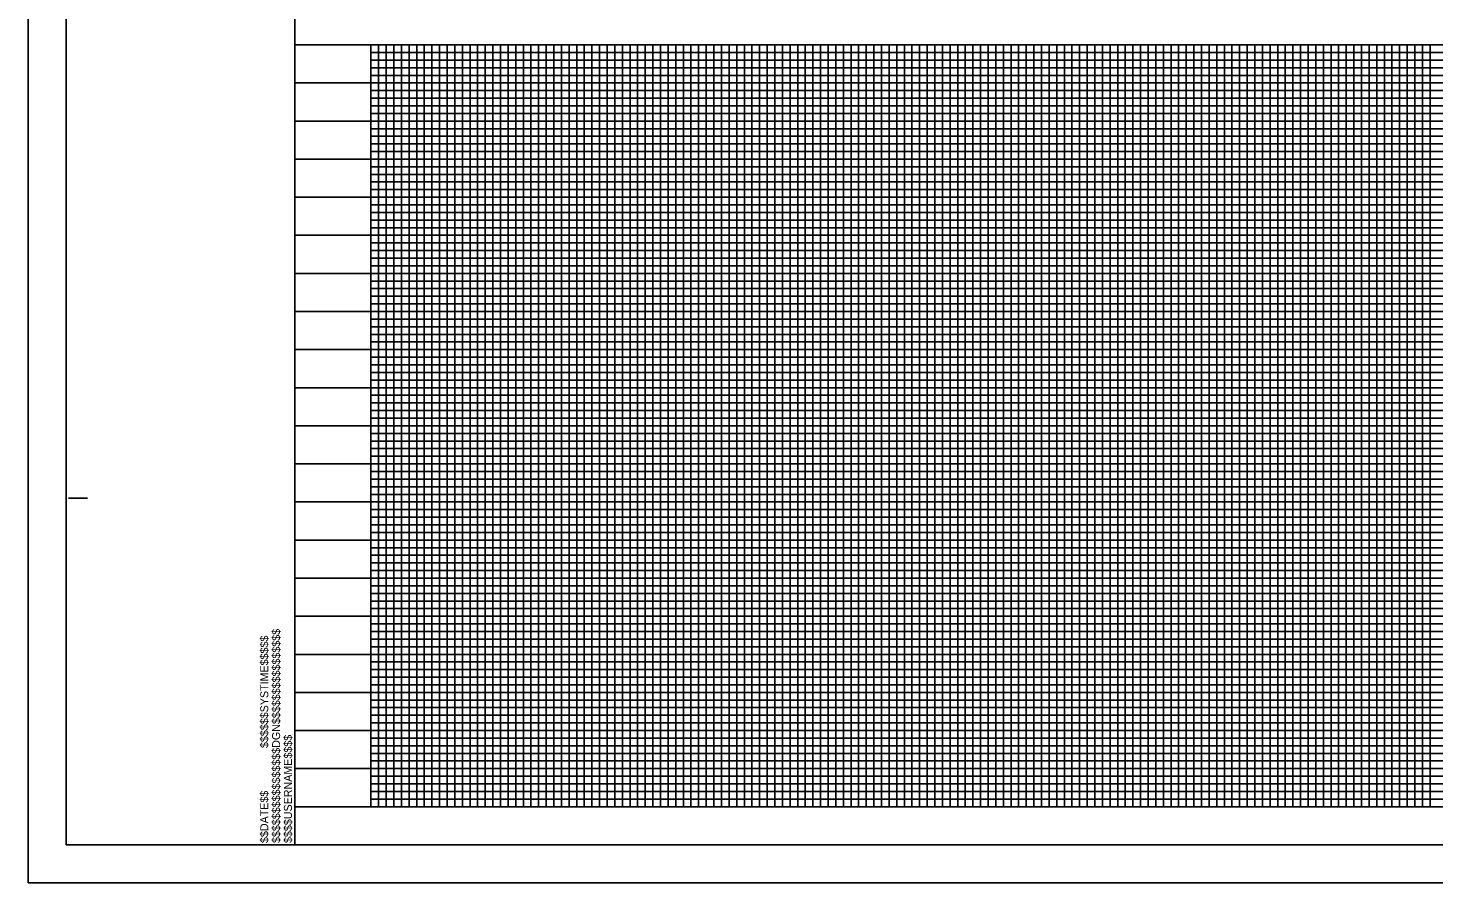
# Model space of a CAD drawing. Extents: x 2474053 to 2475957, y 620456 to 621556.
# Drawn here: x 2474053 to 2474975, y 620456 to 621017 of the extents above; entities that cross this region are included whole.
import ezdxf

# ---------------------------------------------------------------- set-up
doc = ezdxf.new("R2010")
doc.units = 0
for name, color, linetype in [('Old_Level_18', 7, 'Continuous'), ('Old_Level_40', 7, 'Continuous'), ('Old_Level_41', 7, 'Continuous'), ('Old_Level_62', 7, 'Continuous'), ('Old_Level_63', 7, 'Continuous'), ('Scratch_Level_3', 7, 'Continuous'), ('Sheet Layout Profile Border Port 2', 7, 'Continuous'), ('Sheet Profile CELL', 7, 'Continuous'), ('Sheet Profile Grid Major CELL', 7, 'Continuous'), ('Sheet Profile Grid Middle CELL', 7, 'Continuous'), ('Sheet Profile Grid Minor CELL', 7, 'Continuous')]:
    doc.layers.add(name, color=color, linetype=linetype)

msp = doc.modelspace()

# ---------------------------------------------------------------- linework, layer by layer
at = {"layer": 'Old_Level_18'}
msp.add_line((2474227.88, 620481.13), (2474227.88, 620481.13), dxfattribs=at)
msp.add_line((2474227.88, 620481.13), (2474227.88, 620481.13), dxfattribs=at)
msp.add_line((2474227.88, 620481.13), (2474227.88, 620481.13), dxfattribs=at)
msp.add_lwpolyline([(2475727.88, 621531.13), (2474227.88, 621531.13), (2474227.88, 620481.13), (2475727.88, 620481.13)], close=True, dxfattribs=at)
at = {"layer": 'Old_Level_40'}
msp.add_line((2474227.88, 620481.13), (2474227.88, 620481.13), dxfattribs=at)
msp.add_line((2474227.88, 620481.13), (2474227.88, 620481.13), dxfattribs=at)
msp.add_line((2474227.88, 620481.13), (2474227.88, 620481.13), dxfattribs=at)
msp.add_line((2474227.88, 620481.13), (2474227.88, 620481.13), dxfattribs=at)
msp.add_line((2474227.88, 620481.13), (2474227.88, 620481.13), dxfattribs=at)
at = {"layer": 'Old_Level_41'}
msp.add_line((2474079.38, 620708.63), (2474091.88, 620708.63), dxfattribs=at)
at = {"layer": 'Old_Level_62'}
msp.add_lwpolyline([(2474077.88, 620481.13), (2475727.88, 620481.13), (2475727.88, 621531.13), (2474077.88, 621531.13)], close=True, dxfattribs=at)
at = {"layer": 'Old_Level_63'}
msp.add_lwpolyline([(2474052.88, 620456.13), (2475752.88, 620456.13), (2475752.88, 621556.13), (2474052.88, 621556.13)], close=True, dxfattribs=at)
at = {"layer": 'Scratch_Level_3'}
msp.add_lwpolyline([(2474227.88, 621531.13), (2474227.88, 620481.13), (2475727.88, 620481.13), (2475727.88, 621274.49), (2475527.83, 621274.49), (2475527.83, 621531.13)], close=True, dxfattribs=at)
at = {"layer": 'Sheet Layout Profile Border Port 2'}
msp.add_lwpolyline([(2474277.88, 621006.13), (2475677.88, 621006.13), (2475677.88, 620506.13), (2474277.88, 620506.13)], close=True, dxfattribs=at)
at = {"layer": 'Sheet Profile CELL'}
for p, q in [((2474227.88, 621006.13), (2475727.88, 621006.13)), ((2475727.88, 620506.13), (2474227.88, 620506.13))]:
    msp.add_line(p, q, dxfattribs=at)
at = {"layer": 'Sheet Profile Grid Major CELL'}
for p, q in [((2474277.88, 621006.13), (2474277.88, 620506.13)), ((2474327.88, 620506.13), (2474327.88, 621006.13)), ((2474377.88, 621006.13), (2474377.88, 620506.13)), ((2474427.88, 620506.13), (2474427.88, 621006.13)), ((2474477.88, 621006.13), (2474477.88, 620506.13)), ((2474527.88, 620506.13), (2474527.88, 621006.13)), ((2474577.88, 621006.13), (2474577.88, 620506.13)), ((2474627.88, 620506.13), (2474627.88, 621006.13)), ((2474677.88, 621006.13), (2474677.88, 620506.13)), ((2474727.88, 620506.13), (2474727.88, 621006.13)), ((2474777.88, 621006.13), (2474777.88, 620506.13)), ((2474827.88, 620506.13), (2474827.88, 621006.13)), ((2474877.88, 621006.13), (2474877.88, 620506.13)), ((2474927.88, 620506.13), (2474927.88, 621006.13)), ((2475727.88, 620956.13), (2474227.88, 620956.13)), ((2475727.88, 620906.13), (2474227.88, 620906.13)), ((2474227.88, 620856.13), (2475727.88, 620856.13)), ((2475727.88, 620806.13), (2474227.88, 620806.13)), ((2474227.88, 620756.13), (2475727.88, 620756.13)), ((2475727.88, 620706.13), (2474227.88, 620706.13)), ((2474227.88, 620656.13), (2475727.88, 620656.13)), ((2475727.88, 620606.13), (2474227.88, 620606.13)), ((2474227.88, 620556.13), (2475727.88, 620556.13)), ((2475727.88, 620506.13), (2474227.88, 620506.13)), ((2474277.88, 620506.13), (2474327.88, 620506.13)), ((2474377.88, 620506.13), (2474427.88, 620506.13)), ((2474477.88, 620506.13), (2474527.88, 620506.13)), ((2474577.88, 620506.13), (2474627.88, 620506.13)), ((2474677.88, 620506.13), (2474727.88, 620506.13)), ((2474777.88, 620506.13), (2474827.88, 620506.13)), ((2474877.88, 620506.13), (2474927.88, 620506.13))]:
    msp.add_line(p, q, dxfattribs=at)
at = {"layer": 'Sheet Profile Grid Middle CELL'}
for p, q in [((2474302.88, 621006.13), (2474302.88, 620506.13)), ((2474352.88, 620506.13), (2474352.88, 621006.13)), ((2474402.88, 621006.13), (2474402.88, 620506.13)), ((2474452.88, 620506.13), (2474452.88, 621006.13)), ((2474502.88, 621006.13), (2474502.88, 620506.13)), ((2474552.88, 620506.13), (2474552.88, 621006.13)), ((2474602.88, 621006.13), (2474602.88, 620506.13)), ((2474652.88, 620506.13), (2474652.88, 621006.13)), ((2474702.88, 621006.13), (2474702.88, 620506.13)), ((2474752.88, 620506.13), (2474752.88, 621006.13)), ((2474802.88, 621006.13), (2474802.88, 620506.13)), ((2474852.88, 620506.13), (2474852.88, 621006.13)), ((2474902.88, 621006.13), (2474902.88, 620506.13)), ((2474952.88, 620506.13), (2474952.88, 621006.13)), ((2474227.88, 620981.13), (2475727.88, 620981.13)), ((2475727.88, 620931.13), (2474227.88, 620931.13)), ((2474227.88, 620881.13), (2475727.88, 620881.13)), ((2475727.88, 620831.13), (2474227.88, 620831.13)), ((2474227.88, 620781.13), (2475727.88, 620781.13)), ((2475727.88, 620731.13), (2474227.88, 620731.13)), ((2474227.88, 620681.13), (2475727.88, 620681.13)), ((2475727.88, 620631.13), (2474227.88, 620631.13)), ((2474227.88, 620581.13), (2475727.88, 620581.13)), ((2475727.88, 620531.13), (2474227.88, 620531.13)), ((2474302.88, 620506.13), (2474352.88, 620506.13)), ((2474402.88, 620506.13), (2474452.88, 620506.13)), ((2474502.88, 620506.13), (2474552.88, 620506.13)), ((2474602.88, 620506.13), (2474652.88, 620506.13)), ((2474702.88, 620506.13), (2474752.88, 620506.13)), ((2474802.88, 620506.13), (2474852.88, 620506.13)), ((2474852.88, 620506.13), (2474852.88, 620506.13)), ((2474902.88, 620506.13), (2474952.88, 620506.13))]:
    msp.add_line(p, q, dxfattribs=at)
at = {"layer": 'Sheet Profile Grid Minor CELL'}
for p, q in [((2474277.88, 621001.13), (2475677.88, 621001.13)), ((2474282.88, 621006.13), (2474282.88, 620506.13)), ((2474287.88, 620506.13), (2474287.88, 621006.13)), ((2474292.88, 621006.13), (2474292.88, 620506.13)), ((2474297.88, 620506.13), (2474297.88, 621006.13)), ((2474307.88, 621006.13), (2474307.88, 620506.13)), ((2474312.88, 620506.13), (2474312.88, 621006.13)), ((2474317.88, 621006.13), (2474317.88, 620506.13)), ((2474322.88, 620506.13), (2474322.88, 621006.13)), ((2474332.88, 621006.13), (2474332.88, 620506.13)), ((2474337.88, 620506.13), (2474337.88, 621006.13)), ((2474342.88, 621006.13), (2474342.88, 620506.13)), ((2474347.88, 620506.13), (2474347.88, 621006.13)), ((2474357.88, 621006.13), (2474357.88, 620506.13)), ((2474362.88, 620506.13), (2474362.88, 621006.13)), ((2474367.88, 621006.13), (2474367.88, 620506.13)), ((2474372.88, 620506.13), (2474372.88, 621006.13)), ((2474382.88, 621006.13), (2474382.88, 620506.13)), ((2474387.88, 620506.13), (2474387.88, 621006.13)), ((2474392.88, 621006.13), (2474392.88, 620506.13)), ((2474397.88, 620506.13), (2474397.88, 621006.13)), ((2474407.88, 621006.13), (2474407.88, 620506.13)), ((2474412.88, 620506.13), (2474412.88, 621006.13)), ((2474417.88, 621006.13), (2474417.88, 620506.13)), ((2474422.88, 620506.13), (2474422.88, 621006.13)), ((2474432.88, 621006.13), (2474432.88, 620506.13)), ((2474437.88, 620506.13), (2474437.88, 621006.13)), ((2474442.88, 621006.13), (2474442.88, 620506.13)), ((2474447.88, 620506.13), (2474447.88, 621006.13)), ((2474457.88, 621006.13), (2474457.88, 620506.13)), ((2474462.88, 620506.13), (2474462.88, 621006.13)), ((2474467.88, 621006.13), (2474467.88, 620506.13)), ((2474472.88, 620506.13), (2474472.88, 621006.13)), ((2474482.88, 621006.13), (2474482.88, 620506.13)), ((2474487.88, 620506.13), (2474487.88, 621006.13)), ((2474492.88, 621006.13), (2474492.88, 620506.13)), ((2474497.88, 620506.13), (2474497.88, 621006.13)), ((2474507.88, 621006.13), (2474507.88, 620506.13)), ((2474512.88, 620506.13), (2474512.88, 621006.13)), ((2474517.88, 621006.13), (2474517.88, 620506.13)), ((2474522.88, 620506.13), (2474522.88, 621006.13)), ((2474532.88, 621006.13), (2474532.88, 620506.13)), ((2474537.88, 620506.13), (2474537.88, 621006.13)), ((2474542.88, 621006.13), (2474542.88, 620506.13)), ((2474547.88, 620506.13), (2474547.88, 621006.13)), ((2474557.88, 621006.13), (2474557.88, 620506.13)), ((2474562.88, 620506.13), (2474562.88, 621006.13)), ((2474567.88, 621006.13), (2474567.88, 620506.13)), ((2474572.88, 620506.13), (2474572.88, 621006.13)), ((2474582.88, 621006.13), (2474582.88, 620506.13)), ((2474587.88, 620506.13), (2474587.88, 621006.13)), ((2474592.88, 621006.13), (2474592.88, 620506.13)), ((2474597.88, 620506.13), (2474597.88, 621006.13)), ((2474607.88, 621006.13), (2474607.88, 620506.13)), ((2474612.88, 620506.13), (2474612.88, 621006.13)), ((2474617.88, 621006.13), (2474617.88, 620506.13)), ((2474622.88, 620506.13), (2474622.88, 621006.13)), ((2474632.88, 621006.13), (2474632.88, 620506.13)), ((2474637.88, 620506.13), (2474637.88, 621006.13)), ((2474642.88, 621006.13), (2474642.88, 620506.13)), ((2474647.88, 620506.13), (2474647.88, 621006.13)), ((2474657.88, 621006.13), (2474657.88, 620506.13)), ((2474662.88, 620506.13), (2474662.88, 621006.13)), ((2474667.88, 621006.13), (2474667.88, 620506.13)), ((2474672.88, 620506.13), (2474672.88, 621006.13)), ((2474682.88, 621006.13), (2474682.88, 620506.13)), ((2474687.88, 620506.13), (2474687.88, 621006.13)), ((2474692.88, 621006.13), (2474692.88, 620506.13)), ((2474697.88, 620506.13), (2474697.88, 621006.13)), ((2474707.88, 621006.13), (2474707.88, 620506.13)), ((2474712.88, 620506.13), (2474712.88, 621006.13)), ((2474717.88, 621006.13), (2474717.88, 620506.13)), ((2474722.88, 620506.13), (2474722.88, 621006.13)), ((2474732.88, 621006.13), (2474732.88, 620506.13)), ((2474737.88, 620506.13), (2474737.88, 621006.13)), ((2474742.88, 621006.13), (2474742.88, 620506.13)), ((2474747.88, 620506.13), (2474747.88, 621006.13)), ((2474757.88, 621006.13), (2474757.88, 620506.13)), ((2474762.88, 620506.13), (2474762.88, 621006.13)), ((2474767.88, 621006.13), (2474767.88, 620506.13)), ((2474772.88, 620506.13), (2474772.88, 621006.13)), ((2474782.88, 621006.13), (2474782.88, 620506.13)), ((2474787.88, 620506.13), (2474787.88, 621006.13)), ((2474792.88, 621006.13), (2474792.88, 620506.13)), ((2474797.88, 620506.13), (2474797.88, 621006.13)), ((2474807.88, 621006.13), (2474807.88, 620506.13)), ((2474812.88, 620506.13), (2474812.88, 621006.13)), ((2474817.88, 621006.13), (2474817.88, 620506.13)), ((2474822.88, 620506.13), (2474822.88, 621006.13)), ((2474832.88, 621006.13), (2474832.88, 620506.13)), ((2474837.88, 620506.13), (2474837.88, 621006.13)), ((2474842.88, 621006.13), (2474842.88, 620506.13)), ((2474847.88, 620506.13), (2474847.88, 621006.13)), ((2474857.88, 621006.13), (2474857.88, 620506.13)), ((2474862.88, 620506.13), (2474862.88, 621006.13)), ((2474867.88, 621006.13), (2474867.88, 620506.13)), ((2474872.88, 620506.13), (2474872.88, 621006.13)), ((2474882.88, 621006.13), (2474882.88, 620506.13)), ((2474887.88, 620506.13), (2474887.88, 621006.13)), ((2474892.88, 621006.13), (2474892.88, 620506.13)), ((2474897.88, 620506.13), (2474897.88, 621006.13)), ((2474907.88, 621006.13), (2474907.88, 620506.13)), ((2474912.88, 620506.13), (2474912.88, 621006.13)), ((2474917.88, 621006.13), (2474917.88, 620506.13)), ((2474922.88, 620506.13), (2474922.88, 621006.13)), ((2474932.88, 621006.13), (2474932.88, 620506.13)), ((2474937.88, 620506.13), (2474937.88, 621006.13)), ((2474942.88, 621006.13), (2474942.88, 620506.13)), ((2474947.88, 620506.13), (2474947.88, 621006.13)), ((2474957.88, 621006.13), (2474957.88, 620506.13)), ((2474962.88, 620506.13), (2474962.88, 621006.13)), ((2474967.88, 621006.13), (2474967.88, 620506.13)), ((2474972.88, 620506.13), (2474972.88, 621006.13)), ((2475677.88, 620996.13), (2474277.88, 620996.13)), ((2474277.88, 620991.13), (2475677.88, 620991.13)), ((2475677.88, 620986.13), (2474277.88, 620986.13)), ((2474277.88, 620976.13), (2475677.88, 620976.13)), ((2475677.88, 620971.13), (2474277.88, 620971.13)), ((2474277.88, 620966.13), (2475677.88, 620966.13)), ((2475677.88, 620961.13), (2474277.88, 620961.13)), ((2474277.88, 620951.13), (2475677.88, 620951.13)), ((2475677.88, 620946.13), (2474277.88, 620946.13)), ((2474277.88, 620941.13), (2475677.88, 620941.13)), ((2475677.88, 620936.13), (2474277.88, 620936.13)), ((2474277.88, 620926.13), (2475677.88, 620926.13)), ((2475677.88, 620921.13), (2474277.88, 620921.13)), ((2474277.88, 620916.13), (2475677.88, 620916.13)), ((2475677.88, 620911.13), (2474277.88, 620911.13)), ((2474277.88, 620901.13), (2475677.88, 620901.13)), ((2475677.88, 620896.13), (2474277.88, 620896.13)), ((2474277.88, 620891.13), (2475677.88, 620891.13)), ((2475677.88, 620886.13), (2474277.88, 620886.13)), ((2474277.88, 620876.13), (2475677.88, 620876.13)), ((2475677.88, 620871.13), (2474277.88, 620871.13)), ((2474277.88, 620866.13), (2475677.88, 620866.13)), ((2475677.88, 620861.13), (2474277.88, 620861.13)), ((2474277.88, 620851.13), (2475677.88, 620851.13)), ((2475677.88, 620846.13), (2474277.88, 620846.13)), ((2474277.88, 620841.13), (2475677.88, 620841.13)), ((2475677.88, 620836.13), (2474277.88, 620836.13)), ((2474277.88, 620826.13), (2475677.88, 620826.13)), ((2475677.88, 620821.13), (2474277.88, 620821.13)), ((2474277.88, 620816.13), (2475677.88, 620816.13)), ((2475677.88, 620811.13), (2474277.88, 620811.28)), ((2474277.88, 620801.13), (2475677.88, 620801.13)), ((2475677.88, 620796.13), (2474277.88, 620796.13)), ((2474277.88, 620791.13), (2475677.88, 620791.13)), ((2475677.88, 620786.13), (2474277.88, 620786.13)), ((2474277.88, 620776.13), (2475677.88, 620776.13)), ((2475677.88, 620771.13), (2474277.88, 620771.13)), ((2474277.88, 620766.13), (2475677.88, 620766.13)), ((2475677.88, 620761.13), (2474277.88, 620761.13)), ((2474277.88, 620751.13), (2475677.88, 620751.13)), ((2475677.88, 620746.13), (2474277.88, 620746.13)), ((2474277.88, 620741.13), (2475677.88, 620741.13)), ((2475677.88, 620736.13), (2474277.88, 620736.13)), ((2474277.88, 620726.13), (2475677.88, 620726.13)), ((2475677.88, 620721.13), (2474277.88, 620721.13)), ((2474277.88, 620716.13), (2475677.88, 620716.13)), ((2475677.88, 620711.13), (2474277.88, 620711.13)), ((2474277.88, 620701.13), (2475677.88, 620701.13)), ((2475677.88, 620696.13), (2474277.88, 620696.13)), ((2474277.88, 620691.13), (2475677.88, 620691.13)), ((2475677.88, 620686.13), (2474277.88, 620686.13)), ((2474277.88, 620676.13), (2475677.88, 620676.13)), ((2475677.88, 620671.13), (2474277.88, 620671.13)), ((2474277.88, 620666.13), (2475677.88, 620666.13)), ((2475677.88, 620661.13), (2474277.88, 620661.13)), ((2474277.88, 620651.13), (2475677.88, 620651.13)), ((2475677.88, 620646.13), (2474277.88, 620646.13)), ((2474277.88, 620641.13), (2475677.88, 620641.13)), ((2475677.88, 620636.13), (2474277.88, 620636.13)), ((2474277.88, 620626.13), (2475677.88, 620626.13)), ((2475677.88, 620621.13), (2474277.88, 620621.13)), ((2474277.88, 620616.13), (2475677.88, 620616.13)), ((2475677.88, 620611.13), (2474277.88, 620611.13)), ((2474277.88, 620601.13), (2475677.88, 620601.13)), ((2475677.88, 620596.13), (2474277.88, 620596.13)), ((2474277.88, 620591.13), (2475677.88, 620591.13)), ((2475677.88, 620586.13), (2474277.88, 620586.13)), ((2474277.88, 620576.13), (2475677.88, 620576.13)), ((2475677.88, 620571.13), (2474277.88, 620571.13)), ((2474277.88, 620566.13), (2475677.88, 620566.13)), ((2475677.88, 620561.13), (2474277.88, 620561.13)), ((2474277.88, 620551.13), (2475677.88, 620551.13)), ((2475677.88, 620546.13), (2474277.88, 620546.13)), ((2474277.88, 620541.13), (2475677.88, 620541.13)), ((2475677.88, 620536.13), (2474277.88, 620536.13)), ((2474277.88, 620526.13), (2475677.88, 620526.13)), ((2475677.88, 620521.13), (2474277.88, 620521.13)), ((2474277.88, 620516.13), (2475677.88, 620516.13)), ((2474277.88, 620511.13), (2475677.88, 620511.13)), ((2474282.88, 620506.13), (2474287.88, 620506.13)), ((2474292.88, 620506.13), (2474297.88, 620506.13)), ((2474307.88, 620506.13), (2474312.88, 620506.13)), ((2474317.88, 620506.13), (2474322.88, 620506.13)), ((2474322.88, 620506.13), (2474332.88, 620506.13)), ((2474332.88, 620506.13), (2474337.88, 620506.13)), ((2474342.88, 620506.13), (2474347.88, 620506.13)), ((2474357.88, 620506.13), (2474362.88, 620506.13)), ((2474367.88, 620506.13), (2474372.88, 620506.13)), ((2474382.88, 620506.13), (2474387.88, 620506.13)), ((2474392.88, 620506.13), (2474397.88, 620506.13)), ((2474407.88, 620506.13), (2474412.88, 620506.13)), ((2474417.88, 620506.13), (2474422.88, 620506.13)), ((2474432.88, 620506.13), (2474437.88, 620506.13)), ((2474442.88, 620506.13), (2474447.88, 620506.13)), ((2474457.88, 620506.13), (2474462.88, 620506.13)), ((2474467.88, 620506.13), (2474472.88, 620506.13)), ((2474482.88, 620506.13), (2474487.88, 620506.13)), ((2474492.88, 620506.13), (2474497.88, 620506.13)), ((2474507.88, 620506.13), (2474512.88, 620506.13)), ((2474517.88, 620506.13), (2474522.88, 620506.13)), ((2474532.88, 620506.13), (2474537.88, 620506.13)), ((2474542.88, 620506.13), (2474547.88, 620506.13)), ((2474557.88, 620506.13), (2474562.88, 620506.13)), ((2474567.88, 620506.13), (2474572.88, 620506.13)), ((2474582.88, 620506.13), (2474587.88, 620506.13)), ((2474592.88, 620506.13), (2474597.88, 620506.13)), ((2474607.88, 620506.13), (2474612.88, 620506.13)), ((2474617.88, 620506.13), (2474622.88, 620506.13)), ((2474632.88, 620506.13), (2474637.88, 620506.13)), ((2474642.88, 620506.13), (2474647.88, 620506.13)), ((2474657.88, 620506.13), (2474662.88, 620506.13)), ((2474667.88, 620506.13), (2474672.88, 620506.13)), ((2474682.88, 620506.13), (2474687.88, 620506.13)), ((2474692.88, 620506.13), (2474697.88, 620506.13)), ((2474707.88, 620506.13), (2474712.88, 620506.13)), ((2474717.88, 620506.13), (2474722.88, 620506.13)), ((2474732.88, 620506.13), (2474737.88, 620506.13)), ((2474742.88, 620506.13), (2474747.88, 620506.13)), ((2474757.88, 620506.13), (2474762.88, 620506.13)), ((2474767.88, 620506.13), (2474772.88, 620506.13)), ((2474782.88, 620506.13), (2474787.88, 620506.13)), ((2474792.88, 620506.13), (2474797.88, 620506.13)), ((2474807.88, 620506.13), (2474812.88, 620506.13)), ((2474817.88, 620506.13), (2474822.88, 620506.13)), ((2474832.88, 620506.13), (2474837.88, 620506.13)), ((2474842.88, 620506.13), (2474847.88, 620506.13)), ((2474857.88, 620506.13), (2474862.88, 620506.13)), ((2474867.88, 620506.13), (2474872.88, 620506.13)), ((2474882.88, 620506.13), (2474887.88, 620506.13)), ((2474892.88, 620506.13), (2474897.88, 620506.13)), ((2474907.88, 620506.13), (2474912.88, 620506.13)), ((2474917.88, 620506.13), (2474922.88, 620506.13)), ((2474932.88, 620506.13), (2474932.88, 620506.13)), ((2474932.88, 620506.13), (2474937.88, 620506.13)), ((2474942.88, 620506.13), (2474947.88, 620506.13)), ((2474957.88, 620506.13), (2474962.88, 620506.13)), ((2474967.88, 620506.13), (2474972.88, 620506.13))]:
    msp.add_line(p, q, dxfattribs=at)

# ---------------------------------------------------------------- texts
at = {"layer": 'Old_Level_41'}
for s, p in [('$$$$$$$$$$$$$$$$DGN$$$$$$$$$$$$$$$$', (2474218.23, 620482.3)), ('$$$$$$SYSTIME$$$$$', (2474210.47, 620544.64)), ('$$$$USERNAME$$$$', (2474225.99, 620482.3)), ('$$DATE$$', (2474210.47, 620482.3))]:
    msp.add_text(s, height=5.25, rotation=90, dxfattribs=at).set_placement(p)

doc.saveas('drawing.dxf')
